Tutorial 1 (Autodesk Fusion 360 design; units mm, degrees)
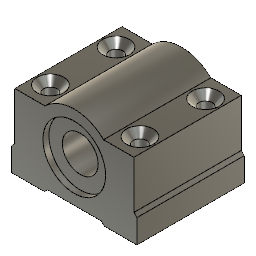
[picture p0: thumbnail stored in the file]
sketch "Sketch2" plane through (0, 0, 0) normal (0, 1, 0) x axis (1, 0, 0)
  line L1 (0, -8) -> (0, 0)
  line L2 (1, -9) -> (0, -8)
  line L3 (1, -25) -> (1, -9)
  line L4 (41, -9) -> (41, -25)
  line L5 (42, -8) -> (41, -9)
  line L6 (42, 0) -> (42, -8)
  line L7 (11.202, -25) -> (1, -25)
  line L8 (41, -25) -> (30.798, -25)
  line L9 (12, -1) -> (11, 0)
  line L10 (30, -1) -> (12, -1)
  line L11 (31, 0) -> (30, -1)
  line L12 (11, 0) -> (0, 0)
  line L13 (42, 0) -> (31, 0)
  circle C1 centre (21, -15) radius 6
  arc A1 centre (21, -15) radius 14 clockwise from (30.798, -25) to (11.202, -25)
  point P1 (0, 0)
  point P2 (0, 0)
  point P10 (0, 0)
  point P18 (31, 0)
  point P3 (0, -8)
  point P5 (1, -25)
  point P6 (41, -25)
  point P11 (21, -15)
  point P15 (11, 0)
  point P9 (42, 0)
  point P17 (30, -1)
  coincident P1 P2
  vertical L1
  parallel L1 L3
  perpendicular L1 L7
  perpendicular L4 L7
  parallel L1 L6
  equal L1 L6
  equal L2 L5
  equal L3 L4
  coincident P1 P10
  horizontal L12
  concentric C1 A1
  collinear L7 L8
  parallel L10 L12
  coincident P18 L12
  collinear L12 L13
  equal L9 L11
  equal L12 L13
  dimension "d1" distance P2 P3 = 8
  dimension "d3" distance L1 L3 = 1
  dimension "d5" angle L5 L6 = 45
  dimension "d16" distance P5 P6 = 40
  dimension "d17" distance L7 L12 = 25
  dimension "d18" distance P11 L12 = 15
  dimension "d19" distance L3 P11 = 20
  dimension "d20" diameter C1 = 12
  dimension "d21" radius A1 = 14
  dimension "d27" distance P1 P15 = 11
  dimension "d31" distance P9 P17 = 1
  dimension "d33" angle L9 L12 = 135
extrude "Extrude2" new body sketch "Sketch2" profile of L1 L2 L3 L8 L4 L5 L6 L13 C1 A1 L9 L10 L11 distance 36
sketch "Sketch3" plane through (0, -18, 0) normal (0, -1, 0) x axis (1, 0, 0)
  line L1 (0, 0) -> (0, 8)
  line L2 (11, 0) -> (0, 0)
  line L3 (12, 1) -> (11, 0)
  line L4 (30, 1) -> (12, 1)
  line L5 (31, 0) -> (30, 1)
  line L6 (42, 0) -> (31, 0)
  line L7 (42, 8) -> (42, 0)
  line L8 (41, 9) -> (42, 8)
  line L9 (41, 25) -> (41, 9)
  line L10 (30.798, 25) -> (41, 25)
  line L11 (1, 25) -> (11.202, 25)
  line L12 (1, 9) -> (1, 25)
  line L13 (0, 8) -> (1, 9)
  circle C1 centre (21, 15) radius 6
  arc A1 centre (21, 15) radius 14 clockwise from (11.202, 25) to (30.798, 25)
  circle C2 centre (21, 15) radius 10.5
  concentric C1 C2
  dimension "d36" diameter C2 = 21
extrude "Extrude3" cut sketch "Sketch3" profile of C1 C2 against normal blind 2
mirror "Mirror1"
hole "Hole1" HoleDepth 25 HoleDiameter 4.5 TipAngle 180 CSDiameter 8.96 CSAngle 90 RefDim1 5 RefDim2 7
rectangular_pattern "R-Pattern1" uSpaceDistance 22 vSpaceDistance -30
